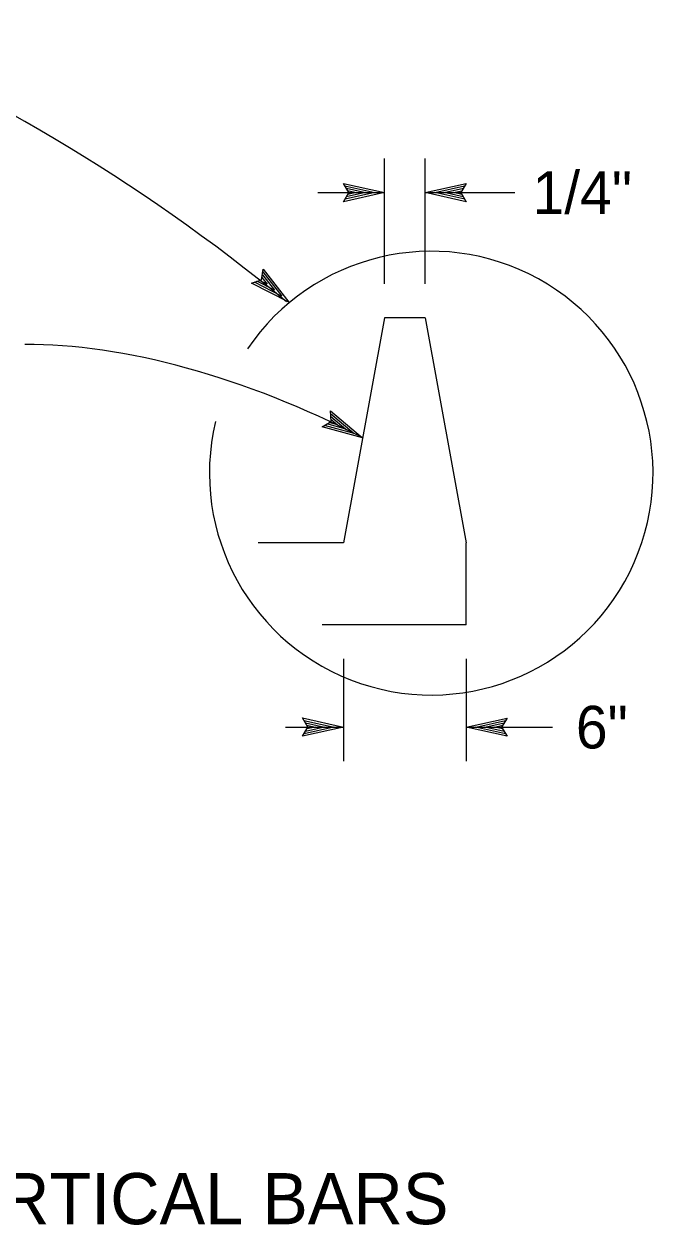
# Model space of a CAD drawing. Extents: x 6709491 to 6710959, y 1869789 to 1870763.
# Drawn here: x 6710373.6 to 6710462.1, y 1870569.6 to 1870738.6 of the extents above; entities that cross this region are included whole.
import ezdxf

# ---------------------------------------------------------------- set-up
doc = ezdxf.new("R2010")
doc.units = 0
for name, color, linetype in [('56 Stg 3 Anno', 7, 'Continuous'), ('57 Undefined', 7, 'Continuous'), ('60 Nongeo Data', 7, 'Continuous')]:
    doc.layers.add(name, color=color, linetype=linetype)

msp = doc.modelspace()

# ---------------------------------------------------------------- linework, layer by layer
at = {"layer": '56 Stg 3 Anno'}
for p, q in [((6710424.29, 1870702.04), (6710424.29, 1870719.66)), ((6710430.05, 1870702.04), (6710430.05, 1870719.66)), ((6710419.3, 1870714.86), (6710418.53, 1870716.15)), ((6710418.53, 1870716.15), (6710418.53, 1870716.15)), ((6710418.53, 1870716.15), (6710424.29, 1870714.86)), ((6710430.05, 1870714.86), (6710435.81, 1870716.14)), ((6710435.81, 1870716.14), (6710435.04, 1870714.86)), ((6710435.81, 1870716.14), (6710435.81, 1870716.14)), ((6710414.95, 1870714.86), (6710424.29, 1870714.86)), ((6710424.29, 1870714.86), (6710418.53, 1870713.58)), ((6710418.53, 1870713.58), (6710419.3, 1870714.86)), ((6710418.74, 1870715.8), (6710422.97, 1870714.86)), ((6710422.96, 1870714.86), (6710418.76, 1870713.93)), ((6710421.64, 1870714.86), (6710418.93, 1870714.26)), ((6710418.96, 1870715.46), (6710421.64, 1870714.86)), ((6710419.13, 1870715.13), (6710420.31, 1870714.86)), ((6710420.31, 1870714.86), (6710419.15, 1870714.61)), ((6710424.29, 1870714.86), (6710424.29, 1870714.86)), ((6710430.05, 1870714.86), (6710442.68, 1870714.86)), ((6710435.81, 1870713.57), (6710430.05, 1870714.86)), ((6710430.05, 1870714.86), (6710430.05, 1870714.86)), ((6710435.6, 1870713.91), (6710431.38, 1870714.86)), ((6710431.39, 1870714.86), (6710435.59, 1870715.79)), ((6710432.7, 1870714.86), (6710435.42, 1870715.46)), ((6710435.38, 1870714.26), (6710432.7, 1870714.86)), ((6710434.03, 1870714.86), (6710435.19, 1870715.11)), ((6710435.21, 1870714.59), (6710434.03, 1870714.86)), ((6710435.04, 1870714.86), (6710435.81, 1870713.57)), ((6710418.53, 1870713.58), (6710418.53, 1870713.58)), ((6710435.81, 1870713.57), (6710435.81, 1870713.57)), ((6710405.6, 1870702.1), (6710407, 1870702.6)), ((6710407.79, 1870701.96), (6710406.73, 1870702.5)), ((6710407, 1870702.6), (6710407.22, 1870704.09)), ((6710407.04, 1870702.92), (6710407.79, 1870701.96)), ((6710407.12, 1870703.28), (6710408.81, 1870701.12)), ((6710407.17, 1870703.69), (6710409.84, 1870700.28)), ((6710407.22, 1870704.09), (6710407.22, 1870704.09)), ((6710407.22, 1870704.09), (6710410.86, 1870699.44)), ((6710410.86, 1870699.44), (6710405.6, 1870702.1)), ((6710405.6, 1870702.1), (6710405.6, 1870702.1)), ((6710409.83, 1870700.29), (6710405.99, 1870702.23)), ((6710408.81, 1870701.12), (6710406.33, 1870702.38)), ((6710410.86, 1870699.44), (6710410.86, 1870699.44)), ((6710416.79, 1870682.66), (6710416.7, 1870684.16)), ((6710416.7, 1870684.16), (6710416.7, 1870684.16)), ((6710416.7, 1870684.16), (6710421.23, 1870680.37)), ((6710415.52, 1870681.88), (6710416.79, 1870682.66)), ((6710418.87, 1870681.59), (6710416.18, 1870682.3)), ((6710417.69, 1870682.2), (6710416.54, 1870682.5)), ((6710416.73, 1870683.76), (6710420.05, 1870680.98)), ((6710416.76, 1870682.98), (6710417.69, 1870682.2)), ((6710416.77, 1870683.35), (6710418.87, 1870681.59)), ((6710421.23, 1870680.37), (6710415.52, 1870681.88)), ((6710415.52, 1870681.88), (6710415.52, 1870681.88)), ((6710420.04, 1870680.98), (6710415.88, 1870682.08)), ((6710421.23, 1870680.37), (6710421.23, 1870680.37)), ((6710418.53, 1870649.24), (6710418.53, 1870634.84)), ((6710435.81, 1870649.24), (6710435.81, 1870634.84)), ((6710413.54, 1870639.64), (6710412.77, 1870640.93)), ((6710412.77, 1870640.93), (6710412.77, 1870640.93)), ((6710412.77, 1870640.93), (6710418.53, 1870639.64)), ((6710412.98, 1870640.59), (6710417.21, 1870639.64)), ((6710413.2, 1870640.24), (6710415.88, 1870639.65)), ((6710435.81, 1870639.64), (6710441.57, 1870640.92)), ((6710437.15, 1870639.65), (6710441.35, 1870640.58)), ((6710438.46, 1870639.64), (6710441.18, 1870640.24)), ((6710441.57, 1870640.92), (6710440.8, 1870639.64)), ((6710441.57, 1870640.92), (6710441.57, 1870640.92)), ((6710410.39, 1870639.64), (6710418.53, 1870639.64)), ((6710418.53, 1870639.64), (6710412.77, 1870638.37)), ((6710412.77, 1870638.37), (6710413.54, 1870639.64)), ((6710412.77, 1870638.37), (6710412.77, 1870638.37)), ((6710417.2, 1870639.64), (6710413, 1870638.71)), ((6710415.88, 1870639.65), (6710413.17, 1870639.04)), ((6710413.37, 1870639.91), (6710414.55, 1870639.65)), ((6710414.55, 1870639.65), (6710413.39, 1870639.39)), ((6710418.53, 1870639.64), (6710418.53, 1870639.64)), ((6710435.81, 1870639.64), (6710447.97, 1870639.64)), ((6710441.57, 1870638.36), (6710435.81, 1870639.64)), ((6710435.81, 1870639.64), (6710435.81, 1870639.64)), ((6710441.36, 1870638.7), (6710437.14, 1870639.64)), ((6710441.14, 1870639.04), (6710438.46, 1870639.64)), ((6710439.79, 1870639.64), (6710440.95, 1870639.9)), ((6710440.97, 1870639.38), (6710439.79, 1870639.64)), ((6710440.8, 1870639.64), (6710441.57, 1870638.36)), ((6710441.57, 1870638.36), (6710441.57, 1870638.36))]:
    msp.add_line(p, q, dxfattribs=at)
msp.add_arc((6710430.89, 1870675.38), 31.22, 166.5593, 145.9552, dxfattribs=at)
for centre, major_axis, end_param in [((6710372.53, 1870658.15), (96.99, -77), 2.189581), ((6710406.94, 1870656.2), (55.44, -27.58), 2.417588)]:
    msp.add_ellipse(centre, major_axis=major_axis, ratio=0.452596, start_param=1.538094, end_param=end_param, dxfattribs=at)
at = {"layer": '60 Nongeo Data'}
for p, q in [((6710424.29, 1870697.24), (6710418.53, 1870665.56)), ((6710430.05, 1870697.24), (6710424.29, 1870697.24)), ((6710430.05, 1870697.24), (6710435.81, 1870665.56)), ((6710418.53, 1870665.56), (6710406.51, 1870665.56)), ((6710435.81, 1870654.04), (6710435.81, 1870665.56)), ((6710435.81, 1870654.04), (6710415.55, 1870654.04))]:
    msp.add_line(p, q, dxfattribs=at)

# ---------------------------------------------------------------- texts
at = {"layer": '57 Undefined'}
for s, height, p in [('1/4"', 6, (6710445.16, 1870711.86)), ('6"', 6, (6710451.26, 1870636.64)), ('VERTICAL BARS', 7.2002, (6710357.34, 1870569.69))]:
    msp.add_text(s, height=height, dxfattribs=at).set_placement(p)

doc.saveas('drawing.dxf')
